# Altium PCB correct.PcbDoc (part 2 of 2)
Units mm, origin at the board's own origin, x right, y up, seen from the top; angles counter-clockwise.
Board outline 184.4 x 190.25 mm, 2 copper layers (Top Layer, Bottom Layer); 180 components, 157 nets, 610 pads, 206 vias.
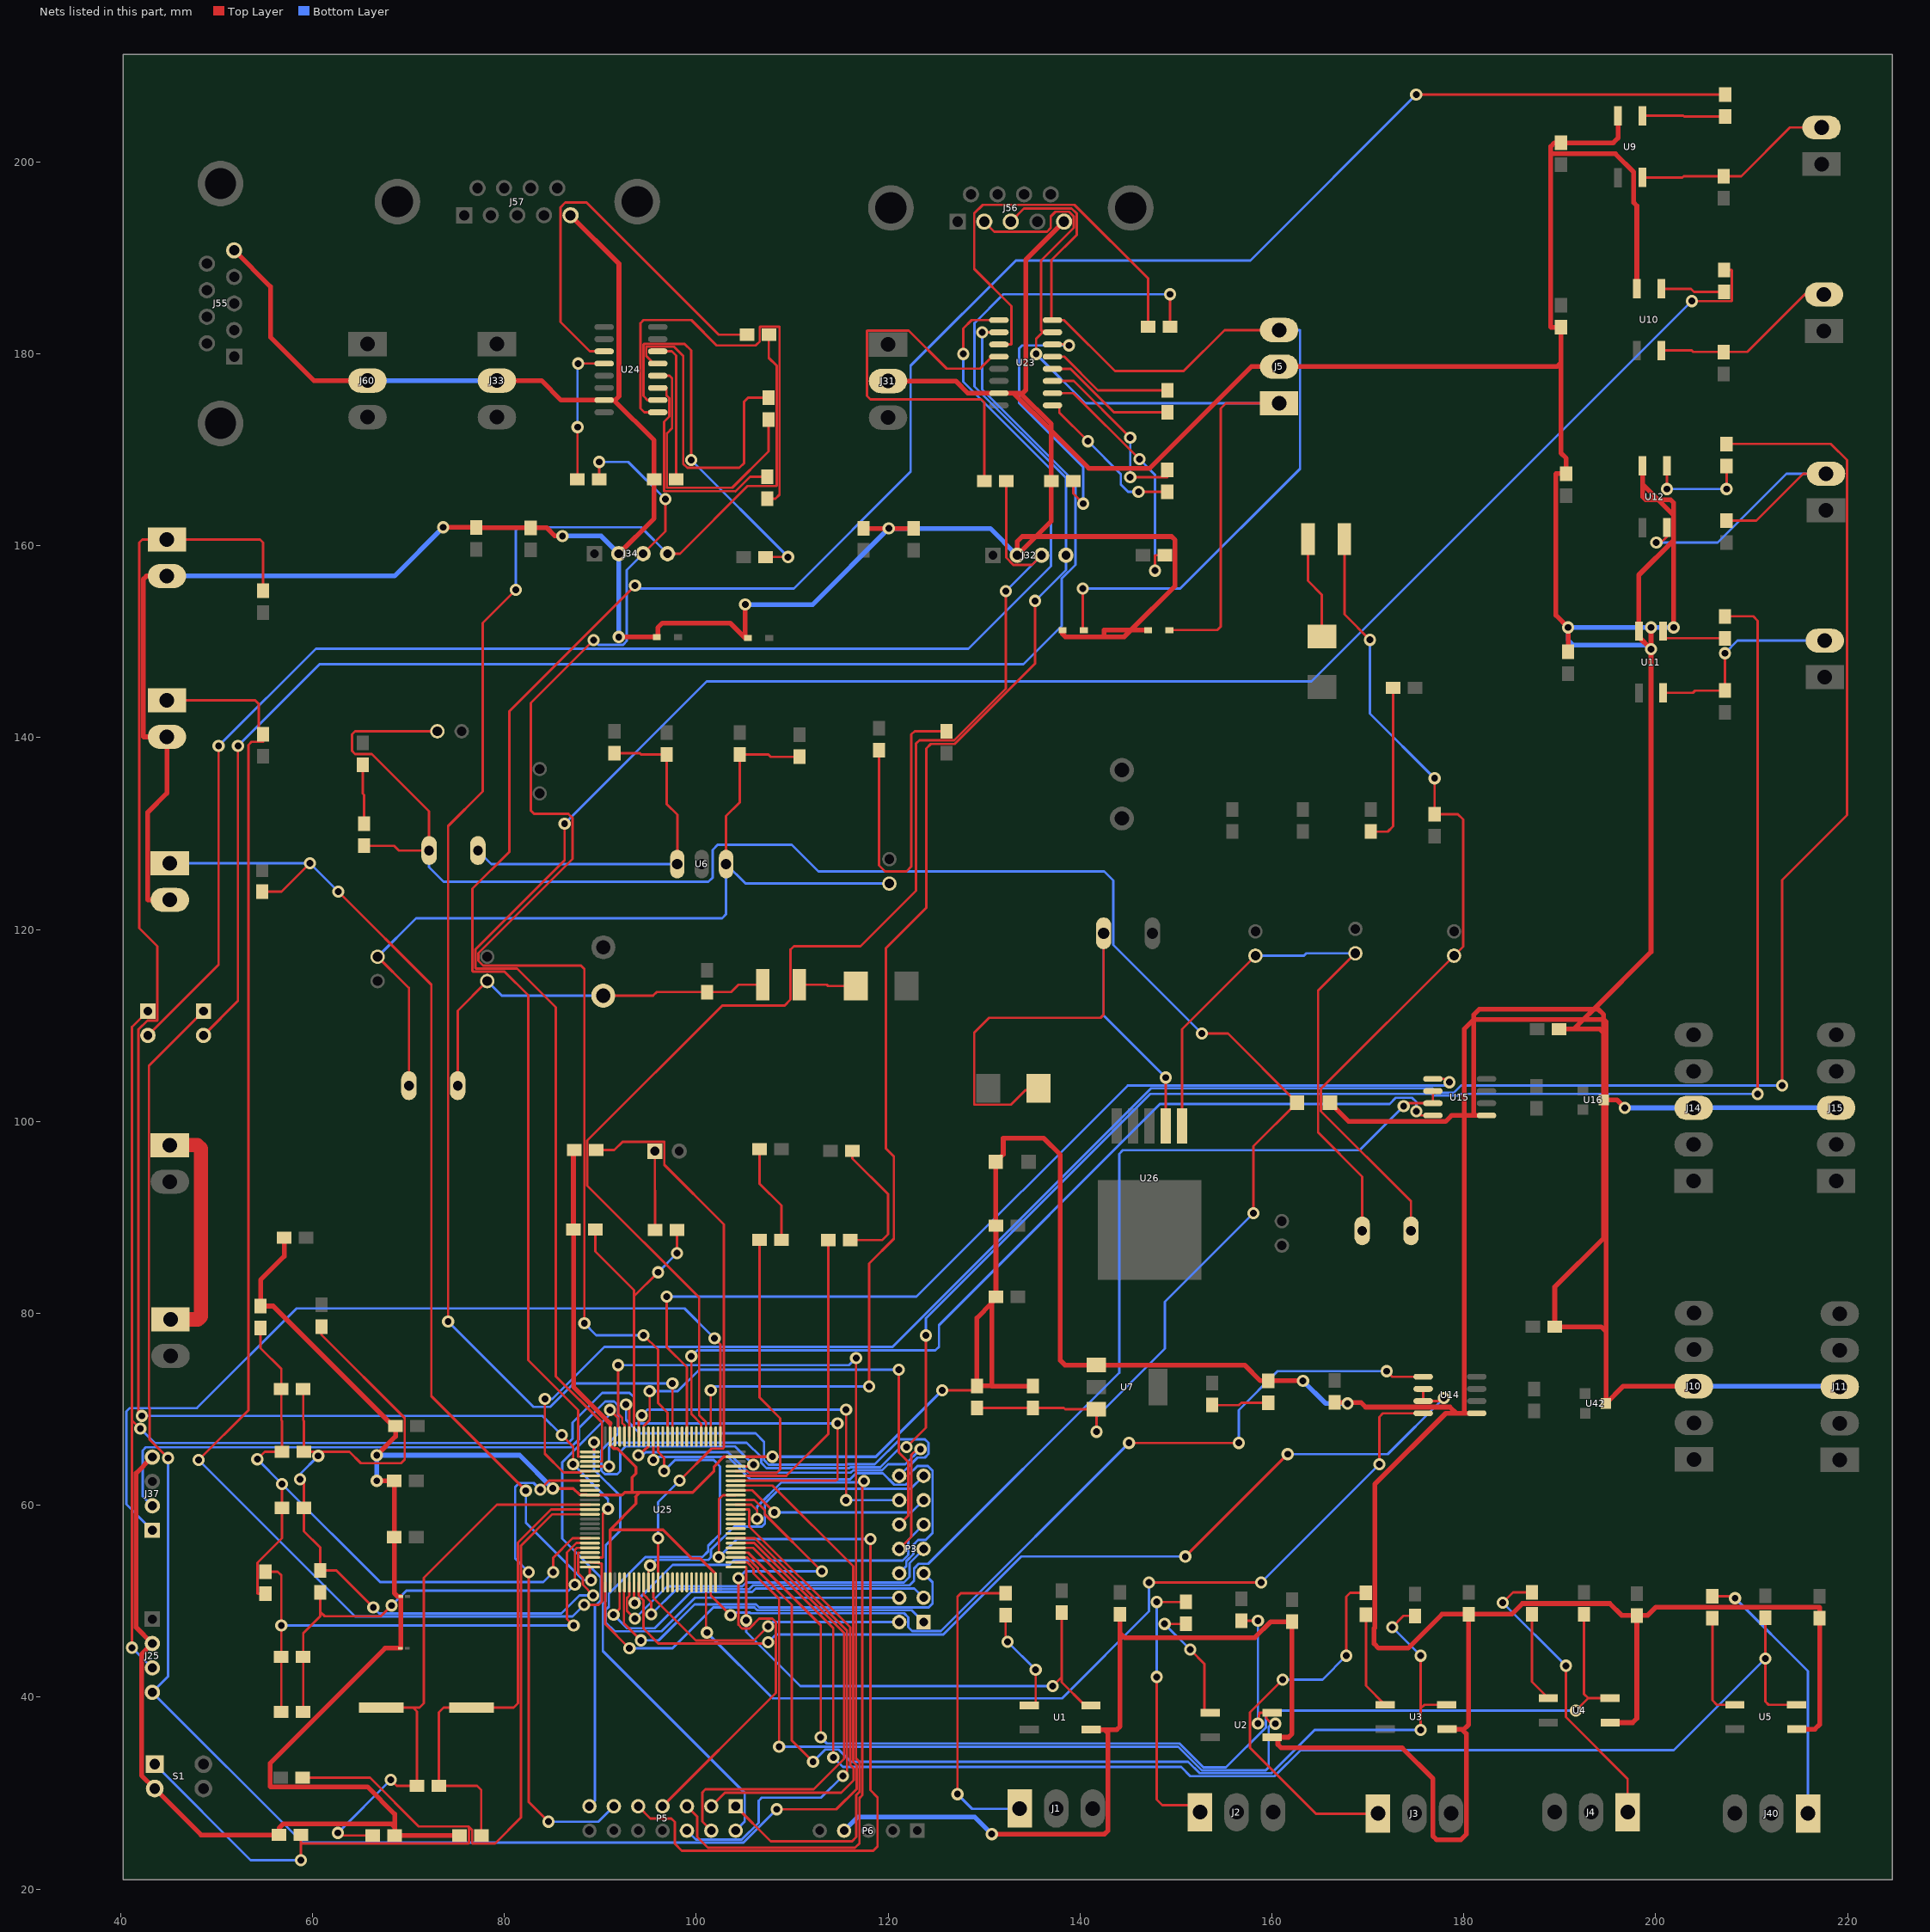
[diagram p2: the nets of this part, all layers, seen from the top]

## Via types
v1: diameter 1.27, hole 0.711, Top Layer to Bottom Layer, 206 vias

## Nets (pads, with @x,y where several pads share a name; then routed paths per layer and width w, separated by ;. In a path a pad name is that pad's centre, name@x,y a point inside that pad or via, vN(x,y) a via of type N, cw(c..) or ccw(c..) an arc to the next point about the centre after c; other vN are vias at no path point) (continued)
GND-SYS: C1.2 C3.2 C7.2 C10.2 C11.2 C14.2 C18.1 C19.1 C20.1 C21.1 C22.1 C24.1 C31.1 C32.2 C34.1 C35.1 C38.2 C41.1 C42.1 C43.2 C47.1 C49.2 C53.2 C55.2 C61.2 C65.2 C67.2 C69.2 C71.1 C72.1 C90.1 C91.1 D40.1 D41.1 D42.1 D43.1 J5.2 J10.3 J11.3 J12.2 J13.2 J14.3 J15.3 J16.2 J25.2 J31.2 J32.2 J33.2 J34.2 J37.4 J55.5 J56.5 J57.5 J60.2 L3.1 LED2.2 P6.4 R24.2 R64.1 R74.2 S1.2 U1.3 U2.3 U3.3 U4.3 U5.3 U7.1 U9.2 U10.2 U11.2 U12.2 U14.5 U15.5 U16.3 U23.15 U24.15 U25.10 U25.27 U25.49 U25.74 U25.99 U42.3 | length 1490.9
  Top Layer w0.254: U25.10@88.595,61.112 88.595,61.063 U25.10@88.92,61.063
  Top Layer w0.3: v1(85.065,61.747) 87.198,61.747 87.833,61.112 U25.10@88.595,61.112 ; U25.10@88.92,61.063 92.266,61.063 92.542,61.339 93.317,61.339 ; U25.27@91.02,51.963 91.02,57.453 ; 91.02,68.529 U25.99@91.02,67.163 91.02,66.267 91.375,65.912 91.81,65.912 93.724,63.999 93.724,63.306 93.317,62.9 93.317,61.339 ; U25.49@102.02,51.963 102.02,52.859 100.422,54.458 99.525,54.458 96.53,57.453 91.02,57.453 ; v1(107.95,65.063) U25.74@104.12,65.063 102.866,65.063 101.852,64.048 101.852,63.56 99.63,61.339 94.107,61.339 ; v1(125.654,71.984) 128.821,71.984 C38.2@129.259,72.421 ; 91.02,57.453 93.724,60.157 93.724,60.849 93.671,60.902 94.107,61.339 ; 93.317,61.339 94.107,61.339
  Top Layer w0.5: J37.4@43.307,65.024 41.631,63.348 41.631,47.269 J25.2@43.307,45.593 42.189,44.475 42.189,31.852 S1.2@43.561,30.48 48.393,25.648 C18.1@56.523,25.648 56.523,26.352 56.967,26.797 68.263,26.797 68.58,26.479 ; J12.2@44.831,156.845 42.71,156.845 42.393,156.528 42.393,140.106 42.418,140.081 J13.2@44.831,140.081 44.831,134.214 42.824,132.207 42.824,123.114 42.85,123.089 J16.2@45.136,123.089 ; J55.5@51.839,190.784 55.626,186.997 55.626,181.737 60.154,177.209 J60.2@65.737,177.209 ; C14.2@57.056,87.878 57.056,85.954 54.595,83.493 L3.1@54.595,80.766 55.905,80.766 68.403,68.268 C11.2@68.665,68.268 68.665,67.183 v1(66.7,65.218) ; v1(66.7,62.553) C10.2@68.538,62.553 68.555,62.553 68.555,56.685 C7.2@68.538,56.685 68.538,50.847 68.897,50.488 C3.2@69.204,50.488 69.204,45.103 C1.2@69.173,45.103 67.573,45.103 55.601,33.131 55.601,30.683 55.626,30.658 65.735,30.658 68.58,27.813 68.58,26.479 ; v1(73.635,161.921) C72.1@77.066,161.921 77.066,161.874 82.743,161.874 C61.2@82.743,161.876 84.404,161.876 85.269,161.011 v1(86.055,161.011) ; C42.1@75.311,25.585 75.311,25.578 68.58,25.578 C41.1@68.58,25.585 68.58,26.479 ; J33.2@79.225,177.209 83.871,177.209 85.903,175.177 U24.15@90.401,175.177 U24.15@91.415,175.177 ; J57.5@86.898,194.439 91.948,189.389 91.948,175.577 91.547,175.177 U24.15@91.415,175.177 ; R64.1@87.309,97.033 87.198,97.033 87.198,88.735 R74.2@87.205,88.735 87.205,72.344 91.02,68.529 ; v1(91.925,150.495) D43.1@95.895,150.495 95.987,150.495 95.987,151.447 96.482,151.943 103.53,151.943 D42.1@105.105,150.368 ; J34.2@91.925,159.175 95.608,162.858 C67.2@95.608,166.922 95.608,170.983 U24.15@91.415,175.177 ; v1(105.105,153.873) D42.1@105.105,150.368 ; D42.1@105.387,150.368 D42.1@105.105,150.368 ; C71.1@117.452,161.798 v1(120.066,161.798) C69.2@122.659,161.798 ; J31.2@119.992,177.165 127.051,177.165 128.321,175.895 U23.15@131.549,175.895 133.096,175.895 ; C38.2@129.259,72.421 C38.2@129.259,72.441 ; v1(130.81,25.73) 142.558,25.73 142.926,26.098 142.926,36.249 142.558,36.618 ; C43.2@135.101,72.421 130.81,72.421 ; D41.1@138.186,151.213 138.176,151.213 138.176,150.812 138.493,150.495 142.501,150.495 ; J56.5@138.333,193.779 134.341,189.787 134.341,176.213 134.023,175.895 133.807,175.895 ; U1.3@141.168,36.618 142.558,36.618 ; C19.1@144.172,48.635 144.172,46.672 ; D40.1@147.109,151.213 145.32,151.213 ; U2.3@160.04,35.825 U2.3@160.63,35.825 ; v1(163.246,72.977) LED2.2@159.63,72.977 158.798,72.977 157.158,74.617 U7.1@141.689,74.617 138.43,74.617 137.947,75.099 137.947,96.52 136.195,98.273 132.004,98.273 132.004,96.571 C55.2@131.216,95.783 131.216,90.729 131.23,90.715 C53.2@131.23,89.132 131.242,89.132 131.242,81.722 C49.2@131.23,81.722 131.23,81.483 130.81,81.063 ; C32.2@166.054,101.956 168.011,100 178.105,100 178.732,100.627 180.035,100.627 ; R24.2@166.542,70.714 v1@167.792,70.714 ; v1(167.894,70.612) v1@167.792,70.714 ; U3.3@178.252,36.666 179.793,36.666 179.912,36.547 ; U14.5@181.358,69.588 180.061,69.588 ; U15.5@182.374,100.627 181.077,100.627 ; C91.1@189.915,109.626 191.477,109.626 ; C35.1@190.881,148.964 v1(190.881,151.486) 189.611,152.756 189.611,167.496 189.636,167.521 C47.1@190.678,167.521 190.678,169.113 190.137,169.654 190.137,179.07 ; U4.3@195.27,37.349 197.604,37.349 198.038,37.782 C22.1@198.038,48.525 ; U9.2@196.088,204.809 196.088,202.494 195.58,201.986 C31.1@190.137,201.986 189.452,201.986 189.078,201.612 189.078,200.812 ; v1(196.794,101.414) 195.963,102.244 U16.3@194.82,102.244 ; U10.2@198.044,186.775 198.044,195.428 197.714,195.758 197.714,198.933 195.809,200.838 189.103,200.838 189.078,200.812 ; U12.2@198.628,168.327 198.628,166.421 ; v1(199.517,151.486) v1(199.517,149.225) ; v1(201.879,151.486) 201.879,160.579 ; J10.3@203.996,72.407 196.623,72.407 U42.3@194.82,70.604 194.82,78.105 ; U5.3@214.701,36.666 216.607,36.666 217.088,37.148 C24.1@217.088,48.223 217.088,49.352 217.063,49.378 200.025,49.378 199.172,48.525 C22.1@198.038,48.525 ; C38.2@129.259,72.441 130.79,72.441 130.81,72.421 ; C38.2@129.259,72.441 129.259,79.512 130.81,81.063 ; 130.81,72.421 130.81,81.063 ; 133.096,175.895 133.807,175.895 ; 133.096,175.895 137.01,171.981 ; 133.807,175.895 137.01,172.692 137.01,171.981 ; 135.41,160.96 137.01,162.56 C65.2@137.01,166.751 137.01,171.981 ; 135.41,160.96 J32.2@133.454,159.004 133.454,160.429 133.985,160.96 135.41,160.96 ; 135.41,160.96 149.542,160.96 149.911,160.591 149.911,155.804 145.32,151.213 ; 137.01,171.981 140.919,168.072 147.269,168.072 157.861,178.664 J5.2@160.757,178.664 189.731,178.664 190.137,179.07 ; 142.501,150.495 144.602,150.495 145.32,151.213 ; 142.501,150.495 142.501,151.213 145.32,151.213 ; 142.558,36.618 143.827,36.618 144.172,36.962 144.172,46.672 ; 144.172,46.672 144.642,46.203 158.229,46.203 159.893,47.867 C20.1@162.097,47.867 162.097,36.195 161.727,35.825 U2.3@160.63,35.825 ; U2.3@160.63,35.825 160.63,35.065 160.972,34.722 173.578,34.722 176.784,31.515 176.784,25.527 177.165,25.146 179.705,25.146 180.264,25.705 180.264,36.195 179.912,36.547 ; v1@167.792,70.714 169.291,70.714 169.774,70.231 178.562,70.231 179.205,69.588 ; 179.205,69.588 180.061,69.588 ; 179.205,69.588 178.13,69.588 170.739,62.197 170.739,47.244 170.663,47.168 170.663,45.58 171.132,45.11 174.193,45.11 177.734,48.652 C21.1@180.512,48.652 ; 179.912,36.547 180.512,37.148 C21.1@180.512,48.652 ; 180.035,100.627 181.077,100.627 ; 180.035,100.627 180.035,109.626 181.051,110.642 ; 180.035,100.627 180.035,69.613 180.061,69.588 ; C21.1@180.512,48.652 185.014,48.652 186.121,49.759 195.224,49.759 196.458,48.525 C22.1@198.038,48.525 ; 181.051,110.642 192.494,110.642 ; 181.051,110.642 181.051,111.125 181.61,111.684 193.535,111.684 ; 181.051,110.642 181.051,100.652 181.077,100.627 ; 189.078,200.812 189.078,182.787 189.103,182.761 C34.1@190.137,182.761 190.137,179.07 ; 191.477,109.626 192.494,110.642 ; 191.477,109.626 194.181,109.626 194.587,109.22 ; 192.494,110.642 193.535,111.684 ; 192.494,110.642 194.587,110.642 ; 193.535,111.684 199.517,117.665 v1(199.517,149.225) ; 193.535,111.684 194.028,111.684 194.587,111.125 194.587,110.642 ; U16.3@194.587,102.244 U16.3@194.82,102.244 ; U16.3@194.587,102.244 194.587,109.22 ; U16.3@194.587,102.244 194.587,87.856 189.486,82.755 C90.1@189.486,78.605 194.32,78.605 194.82,78.105 ; 194.587,109.22 194.587,110.642 ; 194.587,110.642 194.589,110.642 194.82,110.412 U16.3@194.82,102.244 ; 194.82,78.105 U16.3@194.82,102.244 ; 198.628,166.421 200.254,164.795 ; 198.628,166.421 198.628,165.113 198.946,164.795 200.254,164.795 ; v1(199.517,149.225) 198.247,150.495 U11.2@198.247,151.1 198.247,156.947 201.879,160.579 ; 200.254,164.795 201.879,163.17 ; 200.254,164.795 201.549,164.795 201.879,164.465 201.879,163.17 ; 201.879,160.579 201.879,163.17
  Bottom Layer w0.3: v1(107.95,65.063) 118.733,65.063 v1(125.654,71.984)
  Bottom Layer w0.5: J12.2@44.831,156.845 68.559,156.845 v1(73.635,161.921) ; J60.2@65.737,177.209 J33.2@79.225,177.209 ; v1(66.7,62.553) v1(66.7,65.218) 81.594,65.218 v1(85.065,61.747) ; v1(86.055,161.011) 90.09,161.011 J34.2@91.925,159.175 v1(91.925,150.495) ; v1(105.105,153.873) 112.141,153.873 v1(120.066,161.798) 130.66,161.798 J32.2@133.454,159.004 ; P6.4@115.414,26.093 116.829,27.508 129.032,27.508 v1(130.81,25.73) ; v1(163.246,72.977) 165.611,70.612 v1(167.894,70.612) ; v1(196.794,101.414) J14.3@203.962,101.414 204.699,101.414 204.707,101.422 218.076,101.422 218.084,101.414 J15.3@218.821,101.414 ; v1(199.517,149.225) 199.111,149.631 191.427,149.631 190.881,150.177 v1(190.881,151.486) v1(199.517,151.486) v1(201.879,151.486) ; J10.3@203.996,72.407 218.416,72.407 218.465,72.358 J11.3@219.19,72.358
IN1: J1.1 R1.2 | length 32.9
  Top Layer w0.254: v1(127.229,29.896) 127.229,50.482 127.588,50.842 R1.2@132.252,50.842
  Bottom Layer w0.254: v1(127.229,29.896) 128.753,28.372 133.712,28.372 J1.1@133.712,28.396
IN1_1: R7.1 U1.4 U25.51 | length 54.7
  Top Layer w0.254: U25.51@104.12,53.563 105.181,53.563 105.219,53.525 v1(105.219,47.994) ; v1(137.16,41.148) 138.094,42.082 ; R7.1@138.094,48.81 138.094,42.082 ; U1.4@141.142,39.158 140.487,39.158 138.094,41.551 138.094,42.082
  Bottom Layer w0.254: v1(105.219,47.994) 105.219,46.798 110.869,41.148 v1(137.16,41.148)
IN2: J2.1 R2.2 | length 29.1
  Top Layer w0.254: v1(148.006,42.113) 148.006,29.337 148.59,28.753 152.508,28.753 J2.1@152.508,28.015 ; v1(148.006,49.922) R2.2@151.048,49.922
  Bottom Layer w0.254: v1(148.006,42.113) v1(148.006,49.922)
IN2_1: R6.1 U2.4 U25.52 | length 95.6
  Top Layer w0.254: U25.52@104.12,54.063 105.322,54.063 105.983,53.402 105.983,52.896 108.636,50.243 v1(108.636,34.849) ; R6.1@156.826,47.954 v1(158.547,47.954) ; v1(158.547,37.262) 158.699,38.365 U2.4@159.41,38.365 ; U2.4@160.015,38.365 U2.4@159.41,38.365 ; v1(160.363,37.236) 159.957,37.236 159.41,37.782 U2.4@159.41,38.365
  Bottom Layer w0.254: v1(108.636,34.849) 150.241,34.849 152.705,32.385 159.35,32.385 159.668,32.703 159.668,36.884 160.02,37.236 v1(160.363,37.236) ; v1(158.547,37.262) v1(158.547,47.954)
IN3: J3.1 R50.2 | length 40.7
  Top Layer w0.254: v1(161.138,41.834) 157.734,38.43 157.734,34.724 164.594,27.864 171.05,27.864 J3.1@171.05,27.888 ; v1(167.767,44.323) 167.767,50.482 168.151,50.867 R50.2@169.801,50.867
  Bottom Layer w0.254: v1(161.138,41.834) 165.278,41.834 v1(167.767,44.323)
IN3_1: R5.1 U3.4 U25.53 | length 109.8
  Top Layer w0.254: U25.53@104.12,54.563 105.324,54.563 106.444,53.443 106.444,53.152 109.961,49.635 109.961,35.492 v1(112.179,33.274) ; v1(172.542,47.295) 173.724,48.477 R5.1@174.924,48.477 ; v1(175.514,36.576) 175.514,38.825 ; v1(175.514,44.323) 175.514,38.825 ; U3.4@178.226,39.206 175.895,39.206 175.514,38.825
  Bottom Layer w0.254: v1(112.179,33.274) 113.449,34.544 114.846,34.544 116.116,33.274 151.281,33.274 152.474,32.08 159.969,32.08 164.465,36.576 v1(175.514,36.576) ; v1(172.542,47.295) v1(175.514,44.323)
IN4: J4.1 R40.2 | length 30.7
  Top Layer w0.254: v1(184.074,49.86) 185.151,50.938 R40.2@187.116,50.938 ; v1(190.652,43.282) 190.652,37.922 197.085,31.489 J4.1@197.085,28.015
  Bottom Layer w0.254: v1(184.074,49.86) v1(190.652,43.282)
IN4_1: R4.1 U4.4 U25.54 | length 120
  Top Layer w0.254: U25.54@104.12,55.063 105.408,55.063 112.979,47.492 v1(112.979,35.814) ; v1(191.688,38.608) 192.968,39.889 ; R4.1@192.534,48.629 192.534,40.322 192.968,39.889 ; U4.4@195.244,39.889 192.968,39.889
  Bottom Layer w0.254: v1(112.979,35.814) 113.614,35.179 150.368,35.179 152.857,32.69 155.223,32.69 159.363,36.83 159.363,38.268 159.702,38.608 v1(191.688,38.608)
IN5: J40.1 R31.2 | length 28
  Top Layer w0.254: R31.2@205.912,50.509 208.089,50.509 v1(208.28,50.317)
  Bottom Layer w0.254: v1(208.28,50.317) 215.881,42.716 J40.1@215.881,27.888
IN5_1: R3.1 U5.4 U25.55 | length 142.3
  Top Layer w0.254: U25.55@104.12,55.563 105.942,55.563 114.287,47.218 v1(114.287,33.731) ; R3.1@211.436,48.284 v1(211.436,44.024) 211.436,39.542 211.772,39.206 U5.4@214.675,39.206
  Bottom Layer w0.254: v1(114.287,33.731) 115.288,32.73 150.549,32.73 151.504,31.775 160.274,31.775 162.992,34.493 201.905,34.493 v1(211.436,44.024)
IN_24V: P2.1 P4.1 | length 24.2
  Top Layer w1.5: P4.1@45.136,97.536 48.006,97.536 48.387,97.155 48.387,79.692 48.069,79.375 P2.1@45.212,79.375
K1: J12.1 R51.2 U25.23 | length 172.4
  Top Layer w0.254: v1(42.215,69.317) 41.872,69.659 41.872,109.588 42.799,110.515 43.815,110.515 43.84,110.541 43.84,118.262 41.961,120.142 41.961,160.338 42.278,160.655 J12.1@44.831,160.655 54.529,160.655 54.846,160.338 R51.2@54.846,155.298 ; v1(85.979,67.31) 87.173,66.116 v1(87.173,64.262) ; U25.23@88.92,54.563 90.246,54.563 90.272,54.588 90.272,59.106 v1(90.805,59.639)
  Bottom Layer w0.254: v1(42.215,69.317) 83.972,69.317 v1(85.979,67.31) ; v1(87.173,64.262) 90.805,60.63 v1(90.805,59.639)
K2: J13.1 R52.2 U25.24 | length 147.1
  Top Layer w0.254: J13.1@44.831,143.891 54.026,143.891 54.407,143.51 54.407,140.335 R52.2@54.846,140.335 54.846,139.573 53.657,139.573 53.315,139.23 53.315,69.901 v1(48.139,64.726) ; v1(88.316,49.632) 89.852,49.632 90.17,49.949 90.17,53.936 U25.24@88.92,54.063
  Bottom Layer w0.254: v1(48.139,64.726) 64.453,48.412 87.097,48.412 v1(88.316,49.632)
K3: J16.1 R53.2 U25.25 | length 109.5
  Top Layer w0.254: R53.2@54.762,123.952 56.794,123.952 v1(59.741,126.899) ; v1(62.688,123.952) 72.39,114.25 72.39,71.374 v1(82.245,61.519) ; U25.25@88.92,53.563 88.9,53.563 88.9,52.324 v1(89.027,52.197)
  Bottom Layer w0.254: J16.1@45.136,126.899 v1(59.741,126.899) v1(62.688,123.952) ; v1(82.245,61.519) 82.245,58.191 88.24,52.197 v1(89.027,52.197)
L1: R20.2 U25.2 | length 247.1
  Top Layer w0.254: U25.2@88.92,65.063 87.706,65.063 87.681,65.088 87.681,69.926 82.499,75.108 82.499,113.144 80.009,115.634 76.708,115.634 76.683,115.66 76.683,124.257 80.518,128.092 80.518,142.748 v1(93.624,155.854) ; v1(175.04,207.018) R20.2@207.246,207.018
  Bottom Layer w0.254: v1(93.624,155.854) 93.946,155.533 110.172,155.533 122.354,167.715 122.354,178.768 133.324,189.738 157.759,189.738 v1(175.04,207.018)
L1_out: J6.2 R26.2 U9.4 | length 20.8
  Top Layer w0.254: U9.4@198.628,198.382 202.794,198.382 202.921,198.509 R26.2@207.094,198.509 208.915,198.509 213.995,203.589 J6.2@217.297,203.589
L2: R21.2 U25.3 | length 227.8
  Top Layer w0.254: v1(86.284,131.039) 86.284,127.217 76.989,117.922 76.989,115.976 77.026,115.939 81.317,115.939 85.369,111.887 85.369,73.444 90.173,68.641 90.173,64.591 90.145,64.563 U25.3@88.92,64.563 ; v1(203.784,185.496) 207.924,185.496 207.95,185.522 207.95,188.705 207.924,188.73 R21.2@207.137,188.73
  Bottom Layer w0.254: v1(86.284,131.039) 101.092,145.847 164.135,145.847 v1(203.784,185.496)
L2_out: J7.2 R27.2 U10.4 | length 19.5
  Top Layer w0.254: U10.4@200.584,180.348 203.759,180.348 203.909,180.198 R27.2@207.094,180.198 209.542,180.198 215.534,186.19 J7.2@217.551,186.19
L3: R22.2 U25.4 | length 201.3
  Top Layer w0.254: U25.4@88.92,64.063 v1(90.932,64.063) ; v1(121.92,66.065) 123.927,68.072 v1(123.927,77.699) ; R22.2@207.213,152.647 210.185,152.647 210.642,152.19 v1(210.642,102.87)
  Bottom Layer w0.254: v1(90.932,64.063) 90.932,66.04 91.415,66.523 105.268,66.523 106.767,65.024 106.767,64.429 107.315,63.881 115.976,63.881 116.053,63.957 119.177,63.957 121.285,66.065 v1(121.92,66.065) ; v1(123.927,77.699) 123.927,79.486 147.311,102.87 176.667,102.87 176.842,102.694 179.455,102.694 179.631,102.87 v1(210.642,102.87)
L3_out: J8.2 R28.2 U11.4 | length 21.4
  Top Layer w0.254: U11.4@200.787,144.674 203.886,144.674 204.112,144.9 R28.2@207.213,144.9 v1(207.213,148.793)
  Bottom Layer w0.254: v1(207.213,148.793) 208.527,150.107 J8.2@217.627,150.107
L4: R25.2 U25.5 | length 235.4
  Top Layer w0.254: v1(84.226,71.082) 84.226,65.379 86.168,63.437 87.986,63.437 87.986,63.563 U25.5@88.92,63.563 ; R25.2@207.391,170.613 218.261,170.613 219.939,168.935 219.939,131.928 213.182,125.171 v1(213.182,103.759)
  Bottom Layer w0.254: v1(84.226,71.082) 84.996,71.082 90.418,76.505 120.472,76.505 147.423,103.456 176.691,103.456 177.147,102.999 178.945,102.999 179.705,103.759 v1(213.182,103.759)
L4_out: J9.2 R29.2 U12.4 | length 35.4
  Top Layer w0.254: v1(200.076,160.325) 200.558,160.325 201.168,160.934 U12.4@201.168,161.901 ; R29.2@207.391,162.612 210.49,162.612 215.384,167.506 J9.2@217.754,167.506
  Bottom Layer w0.254: v1(200.076,160.325) 206.451,160.325 213.633,167.506 J9.2@217.754,167.506
LED1: LED4.2 U25.71 | length 29.7
  Top Layer w0.254: U25.71@104.12,63.563 105.359,63.563 105.554,63.368 108.402,63.368 108.763,63.729 108.763,69.063 106.589,71.236 LED4.2@106.589,87.657
LED2: LED5.2 U25.70 | length 31.7
  Top Layer w0.254: U25.70@104.12,63.063 109.393,63.063 113.758,67.428 LED5.2@113.758,87.633
MCU_RX: J25.3 S14.1 U25.69 | length 167
  Top Layer w0.254: v1(41.199,45.161) 41.199,68.859 ; v1(42.062,67.996) 41.199,68.859 ; S14.1@42.85,111.506 41.199,109.855 41.199,68.859 ; U25.69@104.12,62.563 114.589,62.563 114.732,62.705 v1(114.732,68.543)
  Bottom Layer w0.254: v1(41.199,45.161) J25.3@43.307,43.053 ; v1(42.062,67.996) 43.561,66.497 86.677,66.497 87.122,66.942 87.122,68.631 90.213,71.722 93.05,71.722 93.52,71.252 93.52,68.686 93.662,68.543 v1(114.732,68.543)
MCU_TX: J25.4 S15.1 U25.68 | length 196.1
  Top Layer w0.254: v1(44.958,64.922) 43.028,66.853 43.028,70.129 42.951,70.206 42.951,105.816 S15.1@48.641,111.506 ; U25.68@104.12,62.063 107.939,62.063 116.357,53.645 116.357,33.276 116.711,32.923 116.711,30.429 114.602,28.321 v1(108.382,28.321)
  Bottom Layer w0.254: v1(44.958,64.922) 44.958,42.164 J25.4@43.307,40.513 58.959,24.861 104.921,24.861 v1(108.382,28.321)
NetC8_1: C8.1 C12.1 C13.1 F1.2 L1.1 | length 42
  Top Layer w0.254: L1.1@75.136,103.73 75.136,111.546 C13.1@78.222,114.632 ; C12.1@90.312,113.108 95.504,113.108 95.885,113.489 C8.1@101.125,113.489 103.632,113.489 104.394,114.251 F1.2@106.929,114.251
  Bottom Layer w0.254: C13.1@78.222,114.632 79.746,113.108 C12.1@90.312,113.108
NetC17_1: C17.1 C30.1 C33.1 C37.1 L1.2 U6.1 | length 94.4
  Top Layer w0.254: C17.1@66.792,117.172 70.056,113.907 L1.2@70.056,103.73 ; U6.1@103.114,126.824 103.114,131.826 104.536,133.249 C37.1@104.536,138.254 107.518,138.254 107.772,138 C33.1@110.778,138
  Bottom Layer w0.254: C17.1@66.792,117.172 70.803,121.183 102.694,121.183 103.114,121.602 U6.1@103.114,126.824 105.146,124.792 C30.1@120.132,124.792
NetC45_1: C45.1 C46.1 L4.1 U6.3 | length 38.8
  Top Layer w0.254: C46.1@91.474,138.381 94.132,138.381 94.259,138.254 C45.1@96.935,138.254 96.935,133.073 98.029,131.978 U6.3@98.029,126.82
  Bottom Layer w0.254: L4.1@77.239,128.238 78.657,126.82 U6.3@98.029,126.82
NetC60_2: C60.2 U24.2 | length 40.4
  Top Layer w0.254: U24.2@95.989,175.177 94.932,175.177 94.491,175.619 94.491,181 94.535,181.044 98.787,181.044 99.466,180.365 v1(99.466,168.935) ; C60.2@107.244,158.812 107.244,158.826 v1(109.576,158.826)
  Bottom Layer w0.254: v1(99.466,168.935) v1(109.576,158.826)
NetC62_1: C62.1 U24.5 | length 34
  Top Layer w0.254: U24.5@95.989,178.987 95.275,178.987 95.275,179.301 94.796,179.781 94.796,180.696 94.84,180.74 97.695,180.74 98.654,179.781 98.654,168.529 99.06,168.123 104.508,168.123 104.978,168.593 104.978,174.999 105.41,175.431 C62.1@107.546,175.431
NetC62_2: C62.2 U24.4 | length 28.7
  Top Layer w0.254: U24.4@95.989,177.717 97.231,177.717 97.488,177.46 97.488,172.24 96.952,171.704 96.952,166.065 96.977,166.04 103.759,166.04 107.546,169.827 C62.2@107.546,173.145
NetC63_1: C63.1 U23.1 | length 16.8
  Top Layer w0.254: U23.1@137.137,174.625 137.846,174.625 137.846,173.863 v1(140.818,170.891) ; v1(146.101,165.608) C63.1@149.101,165.608
  Bottom Layer w0.254: v1(140.818,170.891) 144.253,167.455 144.253,166.37 145.015,165.608 v1(146.101,165.608)
NetC63_2: C63.2 U23.3 | length 19.3
  Top Layer w0.254: U23.3@137.137,177.165 139.344,177.165 v1(145.237,171.272) ; v1(145.237,167.132) 149.101,167.132 C63.2@149.101,167.894
  Bottom Layer w0.254: v1(145.237,167.132) v1(145.237,171.272)
NetC64_2: C64.2 U23.2 | length 26.8
  Top Layer w0.254: U23.2@137.137,175.895 139.319,175.895 v1(146.202,169.012) ; v1(147.828,157.404) 147.828,158.979 147.853,159.004 C64.2@148.847,159.004
  Bottom Layer w0.254: v1(146.202,169.012) 147.828,167.386 v1(147.828,157.404)
NetC65_1: C65.1 U23.6 | length 28.8
  Top Layer w0.254: U23.6@137.137,180.975 138.76,180.975 v1(138.862,180.873) ; C65.1@139.296,166.751 139.296,165.427 v1(140.335,164.389)
  Bottom Layer w0.254: v1(138.862,180.873) 133.985,180.873 133.667,180.556 133.667,174.866 140.335,168.199 v1(140.335,164.389)
NetC66_1: C66.1 U24.1 | length 47.2
  Top Layer w0.254: U24.1@95.989,173.907 94.584,173.907 94.183,174.308 94.183,183.197 94.501,183.515 99.492,183.515 102.133,180.873 106.21,180.873 106.629,181.292 106.629,182.804 106.655,182.829 108.661,182.829 108.687,182.804 108.687,165.329 108.248,164.89 C66.1@107.419,164.89
NetC66_2: C66.2 U24.3 | length 23.4
  Top Layer w0.254: U24.3@95.989,176.447 96.901,176.447 96.901,175.666 97.183,175.384 97.183,173.457 96.647,172.92 96.647,165.684 104.089,165.659 105.606,167.176 C66.2@107.419,167.176
NetC67_1: C67.1 U24.6 | length 15
  Top Layer w0.254: U24.6@95.989,180.257 97.472,180.257 97.894,179.835 C67.1@97.894,166.922
NetC70_1: C70.1 U23.5 | length 13.4
  Top Layer w0.254: U23.5@137.137,179.705 138.354,179.705 141.862,176.197 C70.1@149.119,176.197
NetC70_2: C70.2 U23.4 | length 13.9
  Top Layer w0.254: U23.4@137.137,178.435 139.014,178.435 143.538,173.911 C70.2@149.119,173.911
NetC73_1: C73.1 C74.1 F2.2 L5.1 | length 88.7
  Top Layer w0.254: F2.2@167.568,160.696 167.568,152.853 v1(170.231,150.19) ; L5.1@174.5,88.598 174.5,91.693 165.127,101.067 165.127,103.409 C74.1@178.992,117.275 179.934,118.216 179.934,131.484 179.387,132.03 C73.1@176.96,132.03 v1(176.96,135.763)
  Bottom Layer w0.254: v1(170.231,150.19) 170.231,142.492 v1(176.96,135.763)
NetC76_1: C76.1 C80.1 L5.2 U26.1 | length 63.9
  Top Layer w0.254: U26.1@150.644,99.52 150.644,109.628 C80.1@158.291,117.275 ; C76.1@168.705,117.529 164.822,113.646 164.822,98.856 169.42,94.257 L5.2@169.42,88.598
  Bottom Layer w0.254: C80.1@158.291,117.275 163.347,117.275 163.601,117.529 C76.1@168.705,117.529
NetD2_2: D2.2 F1.1 | length 6
  Top Layer w0.254: F1.1@110.729,114.251 113.614,114.251 113.741,114.124 D2.2@116.65,114.124
NetD8_2: D8.2 F2.1 | length 10.8
  Top Layer w0.254: F2.1@163.768,160.696 163.768,156.335 165.215,154.889 D8.2@165.215,150.545
NetD9_2: D9.2 L6.2 U26.2 | length 60.5
  Top Layer w0.254: D9.2@135.691,103.442 135.691,103.251 134.315,103.251 132.817,101.752 129.007,101.752 128.981,101.778 128.981,109.271 130.518,110.807 142.148,110.807 142.466,111.125 L6.2@142.466,119.607 ; U26.2@148.944,99.52 v1(148.944,104.573)
  Bottom Layer w0.254: L6.2@142.466,119.607 142.466,111.051 v1(148.944,104.573)
NetLED1_1: LED1.1 R30.1 | length 6.2
  Top Layer w0.254: LED1.1@65.244,137.159 65.244,134.161 65.395,134.01 R30.1@65.395,131.015
NetLED2_1: LED2.1 R32.1 | length 5.9
  Top Layer w0.254: R32.1@153.788,70.437 156.566,70.437 156.82,70.691 LED2.1@159.63,70.691
NetLED3_1: LED3.1 R73.1 | length 17
  Top Layer w0.254: R73.1@170.313,130.206 172.085,130.206 172.648,130.769 LED3.1@172.648,145.202
NetLED4_1: LED4.1 R76.1 | length 10.4
  Top Layer w0.254: R76.1@106.606,97.115 106.606,93.506 108.875,91.237 LED4.1@108.875,87.657
NetLED5_1: LED5.1 R77.1 | length 14.4
  Top Layer w0.254: LED5.1@116.044,87.633 119.38,87.633 119.99,88.243 119.99,92.431 116.277,96.143 R77.1@116.277,96.951
NetLED6_1: LED6.1 R90.1 | length 33.4
  Top Layer w0.254: LED6.1@119.069,138.683 119.069,126.682 119.691,126.06 121.92,126.06 122.428,126.568 122.428,140.335 122.76,140.667 R90.1@126.101,140.667
NetR1_1: R1.1 U1.1 | length 11.4
  Top Layer w0.254: R1.1@132.252,48.556 132.252,45.979 v1(132.461,45.771) ; U1.1@134.716,39.158 135.382,39.158 v1(135.382,42.85)
  Bottom Layer w0.254: v1(132.461,45.771) v1(135.382,42.85)
NetR2_1: R2.1 U2.1 | length 13.8
  Top Layer w0.254: v1(148.819,47.636) R2.1@151.048,47.636 ; v1(151.486,44.969) 152.984,43.47 152.984,38.365 U2.1@153.588,38.365
  Bottom Layer w0.254: v1(148.819,47.636) v1(151.486,44.969)
NetR20_1: R20.1 U9.1 | length 8.6
  Top Layer w0.254: U9.1@198.628,204.809 202.895,204.809 202.971,204.732 R20.1@207.246,204.732
NetR21_1: R21.1 U10.1 | length 6.7
  Top Layer w0.254: U10.1@200.584,186.775 203.683,186.775 204.013,186.444 R21.1@207.137,186.444
NetR22_1: R22.1 U11.1 | length 7.2
  Top Layer w0.254: U11.1@200.787,151.1 200.787,150.361 R22.1@207.213,150.361
NetR25_1: R25.1 U12.1 | length 11.1
  Top Layer w0.254: v1(201.168,165.913) U12.1@201.168,168.327 ; v1(207.391,165.913) R25.1@207.391,168.327
  Bottom Layer w0.254: v1(201.168,165.913) v1(207.391,165.913)
NetR31_1: R31.1 U5.1 | length 11.1
  Top Layer w0.254: R31.1@205.912,48.223 205.912,39.668 206.375,39.206 U5.1@208.249,39.206
NetR40_1: R40.1 U4.1 | length 9.5
  Top Layer w0.254: R40.1@187.116,48.652 187.116,41.59 U4.1@188.818,39.889
NetR50_1: R50.1 U3.1 | length 10.2
  Top Layer w0.254: R50.1@169.801,48.581 169.801,41.204 U3.1@171.8,39.206
NetR64_2: R64.2 U25.37 | length 59.4
  Top Layer w0.254: R64.2@89.595,97.033 91.465,97.033 92.324,97.892 96.647,97.892 96.672,97.866 96.672,95.479 102.87,89.281 102.87,66.015 102.768,65.913 101.6,65.913 v1(98.273,62.586) ; v1(96.012,56.566) 96.02,56.558 U25.37@96.02,51.963
  Bottom Layer w0.254: v1(96.012,56.566) 96.012,60.325 v1(98.273,62.586)
NetR74_1: R74.1 R75.1 U25.94 | length 32
  Top Layer w0.254: R74.1@89.491,88.735 89.491,86.462 93.52,82.433 93.52,81.785 ; U25.94@93.52,67.163 93.52,81.785 ; v1(96.012,84.277) 93.52,81.785 ; v1(98,86.266) R75.1@98,88.692
  Bottom Layer w0.254: v1(96.012,84.277) v1(98,86.266)
NetR75_2: R75.2 S7.1 | length 8.2
  Top Layer w0.254: S7.1@95.691,96.906 95.691,92.809 95.714,92.786 R75.2@95.714,88.692
NRST: C18.2 R11.1 S1.1 U25.14 | length 105.7
  Top Layer w0.254: v1(58.809,23.012) 58.809,24.79 ; C18.2@58.809,25.648 58.809,24.79 ; R11.1@58.961,31.617 65.996,31.617 71.082,26.531 76.276,26.531 76.302,26.505 ; U25.14@88.92,59.063 85.009,59.063 81.737,55.791 81.737,27.47 79.032,24.765 76.67,24.765 76.644,24.79 76.644,26.162 76.302,26.505 ; 58.809,24.79 58.834,24.765 76.276,24.765 76.302,24.79 76.302,26.505
  Bottom Layer w0.254: S1.1@43.561,33.02 53.569,23.012 v1(58.809,23.012)
OSC32_IN: U25.8
OSC32_OUT: U25.9
OSCIN: C41.2 R23.2 U25.12 X1.2 | length 61.1
  Top Layer w0.254: v1(62.636,25.857) 62.909,25.585 C41.2@66.294,25.585 ; X1.2@67.177,38.92 67.412,38.92 70.485,38.92 ; v1(68.161,31.382) 68.794,30.749 R23.2@70.889,30.749 70.889,38.516 70.485,38.92 ; U25.12@88.92,60.063 79.215,60.063 71.603,52.451 71.603,39.37 71.152,38.92 70.485,38.92
  Bottom Layer w0.254: v1(62.636,25.857) v1(68.161,31.382)
OSCOUT: C42.2 R23.1 U25.13 X1.1 | length 51.3
  Top Layer w0.254: C42.2@77.597,25.585 77.597,30.304 77.153,30.749 R23.1@73.175,30.749 73.175,38.435 73.66,38.92 X1.1@76.587,38.92 80.982,38.92 81.432,39.37 81.432,56.134 84.861,59.563 U25.13@88.92,59.563
PA3: P3.1 U25.26 | length 41
  Top Layer w0.254: U25.26@90.52,51.963 90.52,47.631 v1(93.039,45.111)
  Bottom Layer w0.254: v1(93.039,45.111) 97.521,45.111 101.78,49.371 106.077,49.371 106.386,49.062 122.468,49.062 P3.1@123.701,47.829
PA4: P3.3 U25.29 | length 38.7
  Top Layer w0.254: v1(91.385,48.59) 92.02,49.225 U25.29@92.02,51.963
  Bottom Layer w0.254: v1(91.385,48.59) 92.795,47.18 95.682,47.18 99.458,50.957 105.829,50.957 106.206,51.333 122.737,51.333 P3.3@123.701,50.369
PA5: P3.5 U25.30 | length 42.5
  Top Layer w0.254: U25.30@92.52,51.963 92.469,50.571 92.469,47.704 v1(94.248,45.924)
  Bottom Layer w0.254: v1(94.248,45.924) 96.089,45.924 99.84,49.675 106.242,49.675 106.551,49.367 124.233,49.367 124.638,49.771 124.638,51.973 P3.5@123.701,52.909
PA6: P3.7 U25.31 | length 38.2
  Top Layer w0.254: U25.31@93.02,51.963 93.02,50.564 92.773,50.317 92.773,49.009 v1(93.599,48.184)
  Bottom Layer w0.254: v1(93.599,48.184) 96.982,51.566 104.817,51.566 105.219,51.968 121.666,51.968 122.225,52.527 122.225,53.973 P3.7@123.701,55.449
PA7: P3.9 U25.32 | length 36.6
  Top Layer w0.254: U25.32@93.52,51.963 93.52,49.888 v1(93.586,49.822)
  Bottom Layer w0.254: v1(93.586,49.822) 97.559,53.795 103.446,53.795 103.881,54.229 121.517,54.229 122.098,54.81 122.098,56.386 P3.9@123.701,57.989
PA8: P3.11 U25.67 | length 21.1
  Top Layer w0.254: U25.67@104.12,61.563 105.842,61.563 v1(108.147,59.258)
  Bottom Layer w0.254: v1(108.147,59.258) 122.43,59.258 P3.11@123.701,60.529
PA15: U25.77
PB0: P3.13 U25.35 | length 35.9
  Top Layer w0.254: U25.35@95.02,51.963 95.02,53.542 v1(95.199,53.721)
  Bottom Layer w0.254: v1(95.199,53.721) 95.785,54.307 101.272,54.307 101.549,54.585 101.549,55.378 103.956,57.785 106.845,57.785 107.163,58.102 107.163,60.198 108.682,61.717 122.349,61.717 P3.13@123.701,63.069
PB1: P3.2 U25.36 | length 29.9
  Top Layer w0.254: U25.36@95.52,51.963 95.52,50.343 99.954,45.909 106.031,45.909 v1(107.493,47.371)
  Bottom Layer w0.254: v1(107.493,47.371) 107.951,47.829 P3.2@121.161,47.829
PB3: P3.4 U25.89 | length 67.5
  Top Layer w0.254: U25.89@96.02,67.163 96.02,65.562 96.655,64.927 v1(96.655,63.576)
  Bottom Layer w0.254: v1(96.655,63.576) 97.798,64.719 101.829,64.719 102.489,64.059 102.489,57.032 101.244,55.788 101.244,55.209 100.647,54.612 94.706,54.612 90.89,50.796 90.89,49.428 90.572,49.111 90.572,47.803 91.499,46.876 96.393,46.876 99.887,50.369 P3.4@121.161,50.369
PB4: P3.6 U25.90 | length 47.5
  Top Layer w0.254: U25.90@95.52,67.163 95.52,64.729 v1(95.529,64.719)
  Bottom Layer w0.254: v1(95.529,64.719) 95.834,65.024 103.327,65.024 105.639,62.713 116.027,62.713 116.662,63.348 119.444,63.348 120.649,62.142 121.832,62.142 122.098,62.408 122.098,63.144 123.063,64.11 124.142,64.11 124.638,63.614 124.638,57.112 123.914,56.388 123.139,56.388 122.631,55.88 122.631,54.913 121.895,54.176 121.895,53.643 P3.6@121.161,52.909
PB5: P3.8 U25.91 | length 45.4
  Top Layer w0.254: v1(93.955,65.202) 95.02,66.142 U25.91@95.02,67.163 ; P3.8@121.161,55.449 122.428,56.717 122.428,65.246 123.031,65.849 v1(123.38,65.849)
  Bottom Layer w0.254: v1(93.955,65.202) 94.386,65.202 94.717,65.532 103.311,65.532 105.446,63.397 116.102,63.397 116.357,63.652 119.38,63.652 119.991,64.263 121.794,64.263 v1(123.38,65.849)
PB6: P3.10 U25.92 | length 48.8
  Top Layer w0.254: U25.92@94.52,67.163 94.52,68.269 95.148,68.897 v1(95.148,71.882) ; v1(121.107,74.143) 121.107,65.507 122.098,64.516 122.098,58.926 P3.10@121.161,57.989
  Bottom Layer w0.254: v1(95.148,71.882) 98.069,71.882 100.33,74.143 v1(121.107,74.143)
PB7: P3.12 U25.93 | length 38.8
  Top Layer w0.254: U25.93@94.02,67.163 94.02,69.052 v1(94.336,69.367) ; v1(115.621,60.529) v1(115.621,69.952)
  Bottom Layer w0.254: v1(94.336,69.367) 94.92,69.952 v1(115.621,69.952) ; v1(115.621,60.529) P3.12@121.161,60.529
PB8: P3.14 U25.95 | length 46
  Top Layer w0.254: v1(92.685,70.498) 93.02,70.162 U25.95@93.02,67.163
  Bottom Layer w0.254: v1(92.685,70.498) 92.685,68.91 94.107,67.488 106.197,67.488 107.071,66.614 107.071,64.709 107.544,64.237 115.722,64.237 115.748,64.262 118.618,64.262 121.234,66.878 123.825,66.878 124.193,66.51 124.193,65.34 123.825,64.972 123.063,64.972 P3.14@121.161,63.069
PB9: P5.1 U25.96 | length 97.3
  Top Layer w0.254: v1(91.872,74.6) 91.872,69.545 92.278,69.139 92.278,68.58 92.52,68.338 U25.96@92.52,67.163 ; P5.1@104.111,28.633 107.751,24.994 116.256,24.994 116.694,25.431 116.694,29.803 117.015,30.124 117.015,33.257 116.662,33.61 v1(116.662,75.336)
  Bottom Layer w0.254: v1(91.872,74.6) 115.926,74.6 v1(116.662,75.336)
PC6: P5.3 U25.63 | length 50.1
  Top Layer w0.254: P5.3@101.571,28.633 102.999,30.061 115.113,30.061 116.406,31.353 116.406,32.574 116.04,32.94 116.04,47.282 105.537,57.785 105.537,59.524 105.498,59.563 U25.63@104.12,59.563
PC7: P5.5 U25.64 | length 76
  Top Layer w0.254: P5.5@99.031,28.633 100.101,27.563 100.101,25.425 101.219,24.308 116.561,24.308 117.018,24.765 117.018,29.488 117.32,29.79 117.32,62.38 v1(117.475,62.535) ; U25.64@104.12,60.063 105.758,60.063 106.35,59.472 v1(106.35,58.598)
  Bottom Layer w0.254: v1(106.35,58.598) 106.35,59.868 108.89,62.408 117.348,62.408 v1(117.475,62.535)
PC8: P5.7 U25.65 | length 54.9
  Top Layer w0.254: P5.7@96.491,28.633 108.306,40.447 108.306,47.828 107.95,48.184 106.568,48.184 105.552,47.168 104.775,47.168 104.394,47.549 v1(104.394,52.4) ; U25.65@104.12,60.563 106.07,60.563 107.163,59.471 107.163,59.055 v1(113.106,53.111)
  Bottom Layer w0.254: v1(104.394,52.4) 105.105,53.111 v1(113.106,53.111)
PC9: P5.9 U25.66 | length 85.3
  Top Layer w0.254: P5.9@93.951,28.633 95.229,27.356 97.396,27.356 97.765,26.987 97.765,24.74 98.501,24.003 118.453,24.003 118.897,24.447 118.897,29.566 118.161,30.302 v1(118.161,56.49) ; v1(102.362,54.61) 102.362,60.642 102.783,61.063 U25.66@104.12,61.063
  Bottom Layer w0.254: v1(102.362,54.61) 104.242,56.49 v1(118.161,56.49)
PC13: P5.11 U25.7 | length 52.4
  Top Layer w0.254: v1(82.55,53.035) 82.55,29.083 v1(84.607,27.026) ; v1(83.744,61.646) 84.661,62.563 U25.7@88.92,62.563
  Bottom Layer w0.254: v1(82.55,53.035) 81.128,54.458 81.128,61.912 81.547,62.332 83.058,62.332 v1(83.744,61.646) ; v1(84.607,27.026) 89.804,27.026 P5.11@91.411,28.633
PD0: U25.81
PD1: U25.82
PD3: U25.84
PD4: U25.85
PD7: U25.88
PD9: P5.4 U25.56 | length 48.9
  Top Layer w0.254: P5.4@101.571,26.093 100.635,27.03 100.635,30.074 100.965,30.404 112.244,30.404 115.418,33.577 115.418,46.685 106.04,56.063 U25.56@104.12,56.063
PD10: P5.6 U25.57 | length 51.6
  Top Layer w0.254: U25.57@104.12,56.563 106.099,56.563 115.722,46.939 115.722,32.233 v1(115.291,31.801)
  Bottom Layer w0.254: P5.6@99.031,26.093 99.959,25.165 104.744,25.165 106.502,26.924 106.502,29.21 106.82,29.527 113.017,29.527 v1(115.291,31.801)
PD11: U25.58
PD12: U25.59
PD13: U25.60
PD14: U25.61
PD15: U25.62
PE0: P5.13 U25.97 | length 48.9
  Top Layer w0.254: v1(91.021,69.939) 91.313,69.939 91.338,69.913 91.338,69.621 91.872,69.088 91.872,68.246 92.02,68.097 U25.97@92.02,67.163
  Bottom Layer w0.254: P5.13@88.871,28.633 89.446,29.208 89.446,49.479 90.081,50.114 90.081,52.464 86.03,56.515 86.03,64.478 91.021,69.469 v1(91.021,69.939)
PE1: U25.98
PE2: P5.2 U25.1 | length 50.3
  Top Layer w0.254: U25.1@88.92,65.563 89.357,65.563 v1(89.357,66.548)
  Bottom Layer w0.254: v1(89.357,66.548) 89.357,63.703 92.075,60.985 92.075,57.353 90.585,55.863 90.585,50.025 90.267,49.708 90.267,44.81 105.054,30.023 105.054,27.036 P5.2@104.111,26.093
PE8: U25.39
PE9: U25.40
PE10: U25.41
PE11: U25.42
PE12: U25.43
PE13: U25.44
PE14: U25.45
PE15: U25.46
Rs232_Rxd1: D41.2 J5.3 J56.3 U23.8 | length 96.4
  Top Layer w0.254: J56.3@132.793,193.779 134.162,195.148 139.14,195.148 139.661,194.627 139.661,192.388 137.033,189.761 137.033,183.515 U23.8@137.137,183.515 138.328,183.515 143.637,178.206 150.8,178.206 155.067,182.474 J5.3@160.757,182.474 ; v1(140.284,155.524) 140.284,151.213 D41.2@140.406,151.213
  Bottom Layer w0.254: v1(140.284,155.524) 150.444,155.524 162.941,168.021 162.941,182.448 162.916,182.474 J5.3@160.757,182.474
Rs232_Txd1: D40.2 J5.1 J56.2 U23.7 | length 91.8
  Top Layer w0.254: J56.2@130.023,193.779 131.067,192.735 136.576,192.735 136.957,193.116 136.957,194.31 137.449,194.802 138.864,194.802 139.356,194.31 139.356,193.128 135.941,189.713 135.941,182.41 ; v1(135.433,179.984) 135.433,181.572 136.106,182.245 ; D40.2@149.329,151.213 154.305,151.213 154.661,151.569 154.661,174.308 155.207,174.854 J5.1@160.757,174.854 ; 135.941,182.41 136.106,182.245 ; 135.941,182.41 U23.7@137.137,182.245 136.106,182.245
  Bottom Layer w0.254: v1(135.433,179.984) 140.564,174.854 J5.1@160.757,174.854
RTC_BATT: U25.6
SWCLK: J37.1 U25.76 | length 91
  Top Layer w0.254: v1(101.91,77.394) 102.52,76.784 U25.76@102.52,67.163
  Bottom Layer w0.254: J37.1@43.307,57.404 40.615,60.096 40.615,69.787 40.957,70.129 47.955,70.129 58.344,80.518 98.786,80.518 v1(101.91,77.394)
SWDIO: J37.2 U25.72 | length 87.3
  Top Layer w0.254: U25.72@104.12,64.063 105.795,64.063 v1(105.954,64.222)
  Bottom Layer w0.254: J37.2@43.307,59.944 42.316,60.935 42.316,65.722 42.634,66.04 86.944,66.04 87.799,66.895 87.799,68.076 90.526,70.802 91.465,70.802 91.872,70.396 91.872,67.481 90.119,65.728 90.119,63.614 90.487,63.246 91.757,63.246 92.075,63.563 92.075,65.59 92.619,66.134 104.042,66.134 v1(105.954,64.222)
U_R\E\2: U14.2 U14.3 U25.33 | length 103.2
  Top Layer w0.254: U25.33@94.02,51.963 94.02,50.557 94.488,50.089 94.488,47.168 96.052,45.604 107.364,45.604 v1(107.493,45.733) ; v1(150.978,54.661) v1(161.646,65.329) ; U14.2@175.77,72.128 U14.3@175.77,70.858 177.614,70.858 v1(177.927,71.171)
  Bottom Layer w0.254: v1(107.493,45.733) 108.293,46.533 125.755,46.533 133.883,54.661 v1(150.978,54.661) ; v1(161.646,65.329) 172.085,65.329 v1(177.927,71.171)
U_R\E\5: U15.2 U15.3 U25.34 | length 122.6
  Top Layer w0.254: U25.34@94.52,51.963 94.52,50.692 95.313,49.898 v1(95.313,48.628) ; v1(173.736,101.587) 174.046,101.897 U15.3@176.786,101.897 U15.2@176.786,103.167
  Bottom Layer w0.254: v1(95.313,48.628) 97.947,51.262 105.524,51.262 105.926,51.664 122.25,51.664 122.706,52.119 122.706,53.414 123.19,53.899 124.181,53.899 144.085,73.803 144.085,96.623 144.463,97.001 169.15,97.001 v1(173.736,101.587)
U_RX1-1: S14.2 U23.9 | length 160.4
  Top Layer w0.254: S14.2@42.85,108.966 50.216,116.332 v1(50.216,139.141) ; v1(127.838,179.984) 127.838,182.639 128.714,183.515 U23.9@131.549,183.515
  Bottom Layer w0.254: v1(50.216,139.141) 60.35,149.276 128.387,149.276 136.982,157.871 136.982,167.957 127.838,177.101 v1(127.838,179.984)
U_RX2: J34.3 S8.1 U25.87 | length 141.3
  Top Layer w0.254: v1(88.341,78.969) 88.341,115.887 87.985,116.244 77.787,116.244 77.294,116.738 77.294,117.556 87.097,127.359 87.097,131.636 86.677,132.055 83.096,132.055 82.753,132.398 82.753,143.612 v1(89.306,150.165) ; S8.1@89.893,166.922 v1(89.893,168.732) ; J34.3@94.465,159.175 96.799,161.509 v1(96.799,164.846) ; v1(94.513,77.724) 96.012,76.225 96.012,70.663 97.02,69.655 U25.87@97.02,67.163
  Bottom Layer w0.254: v1(88.341,78.969) 89.586,77.724 v1(94.513,77.724) ; v1(89.306,150.165) 89.789,149.682 92.38,149.682 92.761,150.063 92.761,157.47 J34.3@94.465,159.175 ; v1(89.893,168.732) 92.913,168.732 v1(96.799,164.846)
U_RX2_1: S8.2 U24.12 | length 14.8
  Top Layer w0.254: S8.2@87.607,166.922 87.63,166.922 v1(87.63,172.364) ; v1(87.681,178.987) U24.12@90.401,178.987
  Bottom Layer w0.254: v1(87.63,172.364) 87.63,178.936 v1(87.681,178.987)
U_RX3: U14.1 U25.48 | length 91.4
  Top Layer w0.254: U25.48@101.52,51.963 101.52,50.601 v1(103.581,48.539) ; v1(145.11,66.497) v1(156.54,66.497) ; v1(171.98,73.977) 172.56,73.398 U14.1@175.77,73.398
  Bottom Layer w0.254: v1(103.581,48.539) 103.848,48.806 105.626,48.806 105.675,48.757 121.677,48.757 122.098,48.336 122.098,47.307 122.517,46.888 125.501,46.888 v1(145.11,66.497) ; v1(156.54,66.497) 156.54,69.926 160.591,73.977 v1(171.98,73.977)
U_RX4: J32.3 S5.1 U25.79 | length 139
  Top Layer w0.254: U25.79@101.02,67.163 101.02,68.652 100.305,69.367 100.305,81.663 88.646,93.322 88.646,98.019 102.718,112.09 109.22,112.09 109.83,112.7 109.83,117.919 110.172,118.262 117.119,118.262 122.911,124.054 122.911,139.382 123.253,139.725 126.898,139.725 132.261,145.088 v1(132.261,155.27) ; S5.1@132.311,166.751 132.311,158.764 133.062,158.013 135.004,158.013 J32.3@135.994,159.004
  Bottom Layer w0.254: v1(132.261,155.27) J32.3@135.994,159.004
U_RX4_1: S5.2 U23.12 | length 43.4
  Top Layer w0.254: S5.2@130.025,166.751 130.025,174.942 129.708,175.26 118.161,175.26 117.805,175.616 117.805,182.397 117.831,182.423 122.145,182.423 126.107,178.46 129.591,178.46 130.835,179.705 U23.12@131.549,179.705
U_RX5: U15.1 U25.83 | length 108.2
  Top Layer w0.254: v1(96.926,81.737) 96.926,76.491 99.02,74.397 U25.83@99.02,67.163 ; U15.1@176.786,104.437 178.164,104.437 v1(178.511,104.089)
  Bottom Layer w0.254: v1(96.926,81.737) 122.957,81.737 144.98,103.761 178.183,103.761 v1(178.511,104.089)
U_TX1-1: S15.2 U23.10 | length 159.7
  Top Layer w0.254: S15.2@48.641,108.966 52.235,112.56 v1(52.235,139.141) ; v1(129.819,182.245) U23.10@131.549,182.245
  Bottom Layer w0.254: v1(52.235,139.141) 60.744,147.65 134.112,147.65 138.1,151.638 138.1,156.591 139.522,158.013 139.522,166.573 129.819,176.276 v1(129.819,182.245)
U_TX2: J34.4 S9.1 U25.86 | length 166.4
  Top Layer w0.254: v1(74.143,79.146) 74.143,130.785 77.749,134.391 77.749,151.943 v1(81.204,155.397) ; J34.4@97.005,159.175 98.317,159.175 105.359,166.218 108.356,166.218 108.382,166.243 108.382,178.765 107.569,179.578 S9.1@107.569,181.992 ; U25.86@97.52,67.163 v1(97.52,72.695)
  Bottom Layer w0.254: v1(74.143,79.146) 83.033,70.256 84.785,70.256 87.224,72.695 v1(97.52,72.695) ; v1(81.204,155.397) 81.204,161.607 81.521,161.925 94.255,161.925 J34.4@97.005,159.175
U_TX2_1: S9.2 U24.11 | length 43.1
  Top Layer w0.254: U24.11@90.401,180.257 88.9,180.257 85.852,183.305 85.852,195.262 86.347,195.758 88.57,195.758 102.336,181.992 S9.2@105.283,181.992
U_TX3: U14.4 U25.47 | length 99.7
  Top Layer w0.254: U25.47@101.02,51.963 101.02,46.833 v1(101.117,46.736) ; v1(147.193,51.968) v1(158.877,51.968) ; v1(171.196,64.287) 171.196,69.215 171.569,69.588 U14.4@175.77,69.588
  Bottom Layer w0.254: v1(101.117,46.736) 107.975,39.878 138.125,39.878 147.193,48.946 v1(147.193,51.968) ; v1(158.877,51.968) v1(171.196,64.287)
U_TX4: J32.4 S6.1 U25.78 | length 171.9
  Top Layer w0.254: U25.78@101.52,67.163 v1(101.52,71.98) ; v1(118.034,72.39) 118.034,85.208 120.599,87.774 120.599,96.342 119.761,97.18 119.761,118.059 123.977,122.276 123.977,138.862 124.46,139.344 126.948,139.344 135.331,147.727 v1(135.331,154.254) ; S6.1@149.378,182.837 v1(149.378,186.207)
  Bottom Layer w0.254: v1(101.52,71.98) 101.93,72.39 v1(118.034,72.39) ; v1(135.331,154.254) 138.534,157.457 J32.4@138.534,159.004 138.534,167.078 129.007,176.606 129.007,183.197 132.017,186.207 v1(149.378,186.207)
U_TX4_1: S6.2 U23.11 | length 43.2
  Top Layer w0.254: U23.11@131.549,180.975 132.842,180.975 132.867,184.963 128.981,188.849 128.981,194.64 129.87,195.529 139.421,195.529 147.092,187.857 S6.2@147.092,182.837
U_TX5: U15.4 U25.80 | length 99.9
  Top Layer w0.254: v1(99.492,75.54) 99.492,69.507 100.52,68.478 U25.80@100.52,67.163 ; v1(175.057,101.067) 175.497,100.627 U15.4@176.786,100.627
  Bottom Layer w0.254: v1(99.492,75.54) 100.101,76.149 124.93,76.149 125.298,76.517 125.298,78.776 148.335,101.813 172.273,101.813 172.923,102.464 174.625,102.464 175.057,102.032 v1(175.057,101.067)
VCC5V: C32.1 C38.1 C43.1 C52.1 L4.2 R30.2 U7.3 | length 201.4
  Top Layer w0.254: R30.2@65.395,128.729 68.529,128.729 69.02,128.238 L4.2@72.159,128.238 72.159,132.336 66.192,138.303 64.453,138.303 64.135,138.62 64.135,140.349 64.453,140.667 C52.1@73.015,140.667 ; C38.1@129.259,70.135 C43.1@135.101,70.135 138.328,70.135 138.447,70.017 U7.3@141.689,70.017 141.732,70.017 v1(141.732,67.666) ; v1(152.69,109.159) 155.423,109.159 C32.1@162.625,101.956 158.09,97.42 v1(158.09,90.449)
  Bottom Layer w0.254: L4.2@72.159,128.238 72.159,126.517 73.683,124.993 101.282,124.993 101.702,125.412 101.702,128.295 102.235,128.829 109.957,128.829 112.725,126.06 142.519,126.06 143.459,125.12 143.459,118.389 v1(152.69,109.159) ; v1(141.732,67.666) 141.732,69.215 148.844,76.327 148.844,81.204 v1(158.09,90.449)
VDDA: C23.1 C27.2 C29.2 L2.2 R17.2 U25.22 | length 86.8
  Top Layer w0.254: v1(58.699,62.713) 59.119,62.293 C29.2@59.119,59.728 59.119,57.3 60.818,55.601 R17.2@60.818,53.207 62.49,53.207 v1(66.345,49.352) ; C23.1@59.04,72.13 59.04,68.888 59.119,68.809 C27.2@59.119,65.57 v1@60.186,65.57 ; v1(60.604,65.151) v1@60.186,65.57 ; L2.2@60.945,78.607 60.945,77.764 69.621,69.088 69.621,64.77 69.24,64.389 65.049,64.389 63.869,65.57 v1@60.186,65.57 ; U25.22@88.92,55.063 87.706,55.063 87.681,55.038 87.681,52.951 88.171,52.461 88.171,51.719 v1(89.268,50.622)
  Bottom Layer w0.254: v1(58.699,62.713) 58.699,63.246 v1(60.604,65.151) ; v1(66.345,49.352) 66.957,48.74 85.938,48.74 87.82,50.622 v1(89.268,50.622)
VREF+: C36.2 C40.2 R17.1 U25.21 | length 46.5
  Top Layer w0.254: C40.2@59.04,38.475 C36.2@59.04,44.19 59.04,46.66 60.818,48.438 60.818,48.895 ; R17.1@60.818,50.921 60.818,48.895 ; v1(68.25,49.555) 67.132,48.438 61.276,48.438 60.818,48.895 ; v1(87.351,51.74) 87.351,55.347 87.567,55.563 U25.21@88.92,55.563
  Bottom Layer w0.254: v1(68.25,49.555) 69.799,51.105 86.716,51.105 v1(87.351,51.74)
VREF-: C36.1 C40.1 R18.1 U25.20 | length 57.2
  Top Layer w0.254: R18.1@55.103,53.08 56.38,53.08 56.754,52.705 v1(56.754,47.473) C36.1@56.754,44.19 C40.1@56.754,38.475 ; v1(87.224,47.473) 86.538,48.158 86.538,55.093 87.508,56.063 U25.20@88.92,56.063
  Bottom Layer w0.254: v1(56.754,47.473) v1(87.224,47.473)
VSSA: C23.2 C27.1 C29.1 L3.2 R18.2 U25.19 | length 72.8
  Top Layer w0.254: v1(54.254,64.795) 55.029,65.57 C27.1@56.833,65.57 56.833,68.809 56.754,68.888 C23.2@56.754,72.13 56.754,74.219 54.595,76.378 L3.2@54.595,78.48 ; R18.2@55.103,50.794 54.305,50.794 54.28,50.819 54.28,54.026 56.833,56.579 C29.1@56.833,59.728 v1(56.833,62.216) ; v1(85.09,53.035) 85.09,54.531 87.122,56.563 U25.19@88.92,56.563
  Bottom Layer w0.254: v1(54.254,64.795) v1(56.833,62.216) 67.056,51.994 84.049,51.994 v1(85.09,53.035)
XCQ_IN_A: U25.38
pads on no net: C48.1 J55.1 J55.4 J55.6 J55.7 J55.8 J55.9 J55.10 J55.11 J56.1 J56.4 J56.6 J56.7 J56.8 J56.9 J56.10 J56.11 J57.1 J57.4 J57.6 J57.7 J57.8 J57.9 J57.10 J57.11 S1.3 S1.4 U24.7 U24.8 U24.9 U24.10 U25.73

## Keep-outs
Keep-Out Layer:
  lines w0.254: 40.259,70.231 40.259,20.955 224.663,20.955 224.663,211.201 40.259,211.201 40.259,164.211 40.259,70.231 ; 40.259,70.231 40.259,70.231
